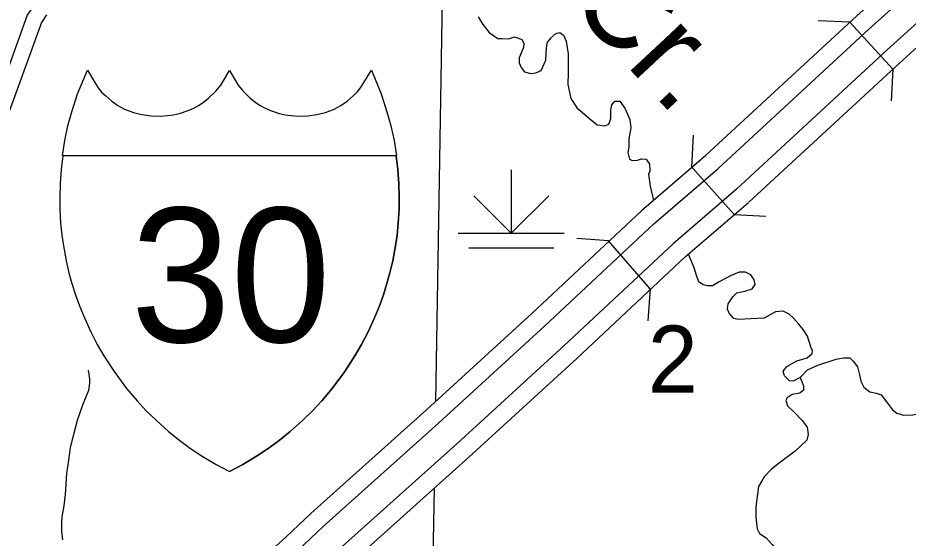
# Model space of a CAD drawing. Extents: x 8749 to 11879, y 13275 to 15339.
# Drawn here: x 10168.7 to 10252.7, y 13809.7 to 13858.8 of the extents above; entities that cross this region are included whole.
import ezdxf

# ---------------------------------------------------------------- set-up
doc = ezdxf.new("R2010")
doc.units = 0
for name, color, linetype in [('Level 19', 7, 'Continuous'), ('Level 23', 7, 'Continuous'), ('Level 32', 7, 'Continuous'), ('Level 35', 7, 'Continuous'), ('Level 37', 7, 'Continuous'), ('Level 39', 7, 'Continuous'), ('Level 44', 7, 'Continuous'), ('Level 45', 7, 'Continuous'), ('Level 5', 7, 'Continuous')]:
    doc.layers.add(name, color=color, linetype=linetype)

msp = doc.modelspace()

# ---------------------------------------------------------------- linework, layer by layer
at = {"layer": 'Level 19'}
msp.add_line((10234.741, 13844.567), (10234.747, 13844.578), dxfattribs=at)
for points in [[(10297.67, 13901.884), (10296.529, 13903.145), (10290.778, 13897.94), (10281.704, 13889.663), (10270.608, 13879.473), (10263.266, 13872.928), (10254.301, 13864.855), (10247.825, 13858.989), (10233.593, 13845.826)], [(10234.747, 13844.578), (10248.973, 13857.735), (10255.44, 13863.594), (10264.4, 13871.662), (10271.748, 13878.213), (10282.851, 13888.409), (10291.921, 13896.682), (10297.67, 13901.884)], [(10300.561, 13898.676), (10299.414, 13899.956), (10293.669, 13894.758), (10284.607, 13886.491), (10273.493, 13876.285), (10266.135, 13869.726), (10257.183, 13861.664), (10250.729, 13855.817), (10236.513, 13842.669)], [(10237.667, 13841.421), (10251.877, 13854.563), (10258.323, 13860.402), (10267.27, 13868.46), (10274.633, 13875.024), (10285.755, 13885.237), (10294.812, 13893.5), (10300.555, 13898.696)], [(10233.6, 13845.824), (10227.555, 13840.617), (10217.198, 13830.925), (10207.241, 13821.827)], [(10208.376, 13820.562), (10218.389, 13829.713), (10228.723, 13839.383), (10234.741, 13844.567)], [(10236.502, 13842.661), (10230.524, 13837.512), (10220.226, 13827.876), (10210.113, 13818.627)], [(10211.249, 13817.362), (10221.429, 13826.676), (10231.702, 13836.289), (10237.654, 13841.415)], [(10207.241, 13821.827), (10196.361, 13812.06), (10193.97, 13809.788)], [(10195.112, 13808.529), (10197.52, 13810.815), (10208.376, 13820.562)], [(10210.113, 13818.627), (10199.293, 13808.913), (10196.854, 13806.599)], [(10197.993, 13805.337), (10200.452, 13807.669), (10211.249, 13817.362)], [(10193.973, 13809.791), (10183.486, 13800.329), (10175.277, 13792.959)]]:
    msp.add_lwpolyline(points, dxfattribs=at)
at = {"layer": 'Level 23'}
for p in [(10172.909, 13845.806), (10204.39, 13845.806)]:
    msp.add_line(p, (10172.929, 13845.806), dxfattribs=at)
for points in [[(10172.909, 13845.806), (10173.128, 13847.257), (10173.42, 13848.631), (10173.795, 13849.965), (10174.337, 13851.674), (10175.263, 13853.907), (10175.972, 13852.724), (10176.282, 13852.228), (10176.598, 13851.83), (10176.983, 13851.457), (10177.554, 13850.975), (10178.133, 13850.563), (10178.772, 13850.204), (10179.593, 13849.891), (10180.401, 13849.695), (10181.263, 13849.577), (10182.178, 13849.551), (10182.838, 13849.604), (10183.377, 13849.669), (10183.961, 13849.796), (10184.776, 13850.096), (10185.302, 13850.322), (10185.746, 13850.557), (10186.177, 13850.844), (10186.689, 13851.244), (10187.362, 13851.902), (10187.833, 13852.477), (10188.224, 13853.117), (10188.66, 13853.87)], [(10172.909, 13845.806), (10173.128, 13847.257), (10173.42, 13848.631), (10173.795, 13849.965), (10174.337, 13851.674), (10175.263, 13853.907), (10175.972, 13852.724), (10176.282, 13852.228), (10176.598, 13851.83), (10176.983, 13851.457), (10177.554, 13850.975), (10178.133, 13850.563), (10178.772, 13850.204), (10179.593, 13849.891), (10180.401, 13849.695), (10181.263, 13849.577), (10182.178, 13849.551), (10182.838, 13849.604), (10183.377, 13849.669), (10183.961, 13849.796), (10184.776, 13850.096), (10185.302, 13850.322), (10185.746, 13850.557), (10186.177, 13850.844), (10186.689, 13851.244), (10187.362, 13851.902), (10187.833, 13852.477), (10188.224, 13853.117), (10188.66, 13853.87)], [(10188.66, 13853.87), (10189.096, 13853.117), (10189.487, 13852.477), (10189.958, 13851.902), (10190.63, 13851.244), (10191.143, 13850.844), (10191.573, 13850.557), (10192.017, 13850.322), (10192.544, 13850.096), (10193.359, 13849.796), (10193.942, 13849.669), (10194.481, 13849.604), (10195.141, 13849.551), (10196.057, 13849.577), (10196.919, 13849.695), (10197.727, 13849.891), (10198.548, 13850.204), (10199.187, 13850.563), (10199.766, 13850.975), (10200.336, 13851.457), (10200.722, 13851.83), (10201.038, 13852.228), (10201.347, 13852.724), (10202.056, 13853.907), (10202.983, 13851.674), (10203.525, 13849.965), (10203.9, 13848.631), (10204.191, 13847.257), (10204.411, 13845.806)], [(10188.66, 13853.87), (10189.096, 13853.117), (10189.487, 13852.477), (10189.958, 13851.902), (10190.63, 13851.244), (10191.143, 13850.844), (10191.573, 13850.557), (10192.017, 13850.322), (10192.544, 13850.096), (10193.359, 13849.796), (10193.942, 13849.669), (10194.481, 13849.604), (10195.141, 13849.551), (10196.057, 13849.577), (10196.919, 13849.695), (10197.727, 13849.891), (10198.548, 13850.204), (10199.187, 13850.563), (10199.766, 13850.975), (10200.336, 13851.457), (10200.722, 13851.83), (10201.038, 13852.228), (10201.347, 13852.724), (10202.056, 13853.907), (10202.983, 13851.674), (10203.525, 13849.965), (10203.9, 13848.631), (10204.191, 13847.257), (10204.411, 13845.806)], [(10172.929, 13845.806), (10172.777, 13844.509), (10172.679, 13843.161), (10172.644, 13841.917), (10172.658, 13840.781), (10172.729, 13839.46), (10172.842, 13838.327), (10172.96, 13837.491), (10173.255, 13835.89), (10173.518, 13834.771), (10173.799, 13833.751), (10174.131, 13832.698), (10174.508, 13831.646), (10174.974, 13830.497), (10175.579, 13829.181), (10176.193, 13827.999), (10176.812, 13826.927), (10177.775, 13825.441), (10178.957, 13823.853), (10179.948, 13822.678), (10180.817, 13821.743), (10181.769, 13820.806), (10182.917, 13819.785), (10183.98, 13818.93), (10184.992, 13818.189), (10186.098, 13817.452), (10187.407, 13816.67), (10188.66, 13816.006)], [(10172.929, 13845.806), (10172.777, 13844.509), (10172.679, 13843.161), (10172.644, 13841.917), (10172.658, 13840.781), (10172.729, 13839.46), (10172.842, 13838.327), (10172.96, 13837.491), (10173.255, 13835.89), (10173.518, 13834.771), (10173.799, 13833.751), (10174.131, 13832.698), (10174.508, 13831.646), (10174.974, 13830.497), (10175.579, 13829.181), (10176.193, 13827.999), (10176.812, 13826.927), (10177.775, 13825.441), (10178.957, 13823.853), (10179.948, 13822.678), (10180.817, 13821.743), (10181.769, 13820.806), (10182.917, 13819.785), (10183.98, 13818.93), (10184.992, 13818.189), (10186.098, 13817.452), (10187.407, 13816.67), (10188.66, 13816.006)], [(10172.929, 13845.806), (10172.777, 13844.509), (10172.679, 13843.161), (10172.644, 13841.917), (10172.658, 13840.781), (10172.729, 13839.46), (10172.842, 13838.327), (10172.96, 13837.491), (10173.255, 13835.89), (10173.518, 13834.771), (10173.799, 13833.751), (10174.131, 13832.698), (10174.508, 13831.646), (10174.974, 13830.497), (10175.579, 13829.181), (10176.193, 13827.999), (10176.812, 13826.927), (10177.775, 13825.441), (10178.957, 13823.853), (10179.948, 13822.678), (10180.817, 13821.743), (10181.769, 13820.806), (10182.917, 13819.785), (10183.98, 13818.93), (10184.992, 13818.189), (10186.098, 13817.452), (10187.407, 13816.67), (10188.66, 13816.006)], [(10204.411, 13845.806), (10172.909, 13845.806)], [(10204.411, 13845.806), (10172.909, 13845.806)], [(10204.411, 13845.806), (10172.909, 13845.806)], [(10204.39, 13845.806), (10204.543, 13844.509), (10204.64, 13843.161), (10204.675, 13841.917), (10204.662, 13840.781), (10204.591, 13839.46), (10204.478, 13838.327), (10204.36, 13837.491), (10204.064, 13835.89), (10203.802, 13834.771), (10203.521, 13833.751), (10203.188, 13832.698), (10202.812, 13831.646), (10202.346, 13830.497), (10201.741, 13829.181), (10201.127, 13827.999), (10200.508, 13826.927), (10199.545, 13825.441), (10198.363, 13823.853), (10197.372, 13822.678), (10196.503, 13821.743), (10195.55, 13820.806), (10194.403, 13819.785), (10193.339, 13818.93), (10192.328, 13818.189), (10191.222, 13817.452), (10189.912, 13816.67), (10188.66, 13816.006)], [(10188.66, 13816.006), (10189.912, 13816.67), (10191.222, 13817.452), (10192.328, 13818.189), (10193.339, 13818.93), (10194.403, 13819.785), (10195.55, 13820.806), (10196.503, 13821.743), (10197.372, 13822.678), (10198.363, 13823.853), (10199.545, 13825.441), (10200.508, 13826.927), (10201.127, 13827.999), (10201.741, 13829.181), (10202.346, 13830.497), (10202.812, 13831.646), (10203.188, 13832.698), (10203.521, 13833.751), (10203.802, 13834.771), (10204.064, 13835.89), (10204.36, 13837.491), (10204.478, 13838.327), (10204.591, 13839.46), (10204.662, 13840.781), (10204.675, 13841.917), (10204.64, 13843.161), (10204.543, 13844.509), (10204.39, 13845.806)], [(10188.66, 13816.006), (10189.912, 13816.67), (10191.222, 13817.452), (10192.328, 13818.189), (10193.339, 13818.93), (10194.403, 13819.785), (10195.55, 13820.806), (10196.503, 13821.743), (10197.372, 13822.678), (10198.363, 13823.853), (10199.545, 13825.441), (10200.508, 13826.927), (10201.127, 13827.999), (10201.741, 13829.181), (10202.346, 13830.497), (10202.812, 13831.646), (10203.188, 13832.698), (10203.521, 13833.751), (10203.802, 13834.771), (10204.064, 13835.89), (10204.36, 13837.491), (10204.478, 13838.327), (10204.591, 13839.46), (10204.662, 13840.781), (10204.675, 13841.917), (10204.64, 13843.161), (10204.543, 13844.509), (10204.39, 13845.806)]]:
    msp.add_lwpolyline(points, dxfattribs=at)
at = {"layer": 'Level 32'}
msp.add_lwpolyline([(10171.397, 13859.121), (10170.912, 13858.402), (10168.376, 13851.378), (10167.759, 13849.64)], dxfattribs=at)
at = {"layer": 'Level 35'}
for points in [[(10212.144, 13858.93), (10212.556, 13858.198), (10213.173, 13857.465), (10213.997, 13856.893), (10214.363, 13856.87), (10214.98, 13856.847), (10215.552, 13857.03), (10215.849, 13856.939), (10216.261, 13856.778), (10216.444, 13856.458), (10216.398, 13856.023), (10215.986, 13855.061), (10215.986, 13854.581), (10216.192, 13854.146), (10216.489, 13853.734), (10217.107, 13853.596), (10217.587, 13853.642), (10218.09, 13853.871), (10218.502, 13854.833), (10218.593, 13856), (10218.685, 13856.527), (10219.028, 13856.962), (10219.371, 13857.282), (10219.577, 13857.396), (10219.828, 13857.442), (10220.194, 13857.19), (10220.446, 13856.618), (10220.629, 13855.428), (10220.629, 13853.642), (10220.583, 13852.543)], [(10220.583, 13852.543), (10220.869, 13851.216), (10221.486, 13850.323), (10221.967, 13849.911), (10222.653, 13849.316), (10223.362, 13848.743), (10224.071, 13848.629), (10224.46, 13848.789), (10224.643, 13849.338), (10224.643, 13850.117), (10224.757, 13850.62), (10225.031, 13850.964), (10225.512, 13850.964), (10225.969, 13850.323), (10226.449, 13849.247), (10226.541, 13848.446), (10226.358, 13847.415), (10226.335, 13846.614)], [(10226.335, 13846.614), (10226.261, 13846.111), (10226.398, 13845.493), (10226.649, 13845.355), (10227.175, 13845.401), (10227.541, 13845.515), (10227.999, 13845.493), (10228.296, 13845.035), (10228.319, 13844.371), (10228.204, 13844.073), (10228.365, 13842.952), (10228.686, 13841.591)], [(10236.155, 13832.49), (10236.543, 13832.867), (10237.298, 13833.028), (10237.984, 13833.234), (10238.259, 13833.646), (10238.19, 13834.103), (10237.847, 13834.561), (10237.367, 13834.813), (10236.749, 13834.813), (10236.017, 13834.493), (10234.874, 13833.897), (10234.233, 13833.531), (10233.753, 13833.531), (10233.364, 13833.623), (10232.953, 13833.897), (10232.77, 13834.401), (10232.518, 13835.225), (10231.966, 13836.516)], [(10243.198, 13825.599), (10242.512, 13824.889), (10241.849, 13824.523), (10241.506, 13824.569), (10241.049, 13825.027), (10240.911, 13825.485), (10241.255, 13825.92), (10242.215, 13826.446), (10243.176, 13826.744), (10243.656, 13827.133), (10243.679, 13827.453), (10243.587, 13827.591), (10243.336, 13828.369), (10243.221, 13828.781), (10242.787, 13829.399), (10242.398, 13829.903), (10241.872, 13830.475), (10241.483, 13830.864), (10240.911, 13831.139), (10240.203, 13831.07), (10239.105, 13830.475), (10237.87, 13830.406), (10236.681, 13830.361), (10236.246, 13830.452), (10235.812, 13830.956), (10235.651, 13831.322), (10235.72, 13831.826), (10236.155, 13832.49)], [(10243.198, 13825.599), (10244.193, 13826.035), (10245.909, 13826.608), (10246.618, 13826.722), (10247.189, 13826.722), (10247.509, 13826.425), (10247.921, 13825.875), (10248.127, 13825.12), (10248.241, 13824.547), (10248.516, 13823.975), (10249.087, 13823.54), (10249.682, 13823.403), (10250.162, 13823.243), (10250.665, 13822.579), (10251.237, 13821.823), (10251.649, 13821.503), (10252.266, 13821.32), (10253.158, 13821.365), (10253.952, 13821.539)], [(10172.886, 13811.727), (10173.077, 13812.747), (10173.186, 13813.839), (10173.322, 13815.803), (10173.513, 13817.058), (10173.676, 13818.231), (10173.922, 13819.268), (10174.331, 13820.85), (10174.821, 13822.296), (10175.393, 13823.688), (10175.502, 13824.354), (10175.502, 13824.736), (10175.421, 13825.172), (10175.359, 13825.565)], [(10242.512, 13824.889), (10242.821, 13824.09), (10242.844, 13823.678), (10242.478, 13823.403), (10241.769, 13823.265), (10241.289, 13822.968), (10241.174, 13822.693), (10241.312, 13822.212), (10241.952, 13821.594), (10242.707, 13820.816), (10243.164, 13820.175), (10243.256, 13819.488), (10243.141, 13818.962), (10242.044, 13817.932), (10240.694, 13816.924), (10239.802, 13816.238), (10239.116, 13815.505)], [(10239.116, 13815.505), (10238.596, 13814.589), (10238.344, 13812.666), (10238.321, 13811.705), (10238.459, 13810.583), (10238.687, 13810.148), (10239.305, 13809.736), (10239.877, 13809.095), (10240.243, 13808.592), (10240.563, 13808.008), (10240.997, 13805.421), (10240.608, 13803.269), (10239.936, 13802.183), (10239.739, 13801.644), (10239.762, 13800.774), (10239.991, 13800.156), (10240.248, 13799.648), (10240.258, 13799.37), (10240.179, 13799.171), (10240.03, 13798.813), (10239.692, 13798.475), (10239.305, 13798.279), (10238.619, 13798.324)], [(10172.941, 13809.544), (10172.832, 13810.363), (10172.859, 13811.099), (10172.886, 13811.727)]]:
    msp.add_lwpolyline(points, dxfattribs=at)
at = {"layer": 'Level 39'}
for p, q in [((10247.213, 13858.419), (10244.216, 13858.559)), ((10251.254, 13853.985), (10247.213, 13858.419)), ((10251.254, 13853.985), (10251.115, 13850.988)), ((10232.293, 13844.75), (10232.464, 13847.746)), ((10232.293, 13844.75), (10236.286, 13840.272)), ((10236.286, 13840.272), (10239.281, 13840.101)), ((10224.428, 13837.771), (10221.436, 13837.987)), ((10228.354, 13833.234), (10224.428, 13837.771)), ((10228.354, 13833.234), (10228.138, 13830.242))]:
    msp.add_line(p, q, dxfattribs=at)
at = {"layer": 'Level 44'}
for p, q in [((10215.258, 13844.494), (10215.258, 13838.494)), ((10215.258, 13838.494), (10211.722, 13842.03)), ((10215.258, 13838.494), (10218.793, 13842.03)), ((10210.258, 13838.494), (10220.258, 13838.494)), ((10211.258, 13837.131), (10219.258, 13837.131))]:
    msp.add_line(p, q, dxfattribs=at)
at = {"layer": 'Level 45'}
msp.add_lwpolyline([(10175.112, 13865.964), (10173.765, 13864.292), (10170.73, 13860.815), (10169.564, 13859.087), (10166.964, 13851.883), (10165.432, 13847.571), (10162.576, 13839.391), (10158.188, 13826.353), (10155.884, 13819.435), (10151.762, 13807.939)], dxfattribs=at)
at = {"layer": 'Level 5'}
for points in [[(10208.843, 13866.412), (10208.11, 13822.62)], [(10207.972, 13814.42), (10207.806, 13804.521), (10207.09, 13773.283)]]:
    msp.add_lwpolyline(points, dxfattribs=at)

# ---------------------------------------------------------------- texts
at = {"layer": 'Level 23'}
msp.add_text('30', height=12.672, dxfattribs=at).set_placement((10179.353, 13828.221))
at = {"layer": 'Level 35'}
msp.add_text('Cr.', height=8.448, rotation=312.99593, dxfattribs=at).set_placement((10220.422, 13860.402))
at = {"layer": 'Level 37'}
msp.add_text('2', height=6.336, dxfattribs=at).set_placement((10228.144, 13823.444))

doc.saveas('drawing.dxf')
